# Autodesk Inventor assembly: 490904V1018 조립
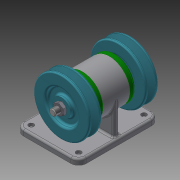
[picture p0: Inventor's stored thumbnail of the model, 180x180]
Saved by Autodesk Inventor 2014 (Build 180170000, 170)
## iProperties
Created: 2019-09
Part Number: 490904V1018 조립
Document SubType Name: Assembly
Designer: kh
Author: kh
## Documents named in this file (10)
- C:\Users\kh\Desktop\490904V1018\490904V1018 조립.iam
- C:\Users\kh\Desktop\490904V1018\본체.ipt
- C:\Users\kh\Desktop\490904V1018\V-벨트풀리.ipt
- C:\Users\kh\Desktop\490904V1018\너트 M10x1.ipt
- C:\Users\kh\Desktop\490904V1018\베어링 6004.ipt
- C:\Users\kh\Desktop\490904V1018\볼트 M4.ipt
- C:\Users\kh\Desktop\490904V1018\오일 실 17 30 5.ipt
- C:\Users\kh\Desktop\490904V1018\축.ipt
- C:\Users\kh\Desktop\490904V1018\커버.ipt
- C:\Users\kh\Desktop\490904V1018\키 5 x 5 x 12.ipt
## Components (2 placed, 1 different names)
1. V-벨트풀리:1 — Insert:14, Mate:5, Insert:16
2. V-벨트풀리:2 — Insert:15, Mate:6, Insert:17
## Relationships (6: Insert 4, Mate 2)
- Insert:14: V-벨트풀리:1
- Mate:5: V-벨트풀리:1
- Insert:15: V-벨트풀리:2
- Mate:6: V-벨트풀리:2
- Insert:16: V-벨트풀리:1
- Insert:17: V-벨트풀리:2
